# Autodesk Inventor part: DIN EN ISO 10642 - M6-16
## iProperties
Created: 2007-08
Part Number: DIN EN ISO 10642 - M6-16
Material: Stahl, weich, unlegiert
Description: Innensechskantschraube mit Senkkopf
Vendor: Autodesk Inc.
Document SubType Name: Modeling
Standard: ISO 10642
Designer: Ulrich
Standards Organization: DIN
Language: de-DE
Size Designation: M6  x  16
Categories: <MemberInstance Version="R10.0.0"><Categories><Category DisplayName="Schrauben" InternalName="e4da775c-781d-43d5-af7c-5136215cf5a6" Mnemonic="FSTN"><Category Di
Author: Ulrich
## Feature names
1. Körper [Revolution]
2. Loch [Extrusion]
3. Fase1 [Chamfer]
